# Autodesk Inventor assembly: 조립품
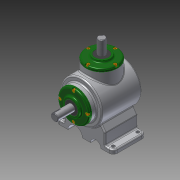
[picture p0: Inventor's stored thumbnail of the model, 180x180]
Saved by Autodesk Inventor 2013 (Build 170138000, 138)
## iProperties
Created: 2018-08
Part Number: 조립품
Document SubType Name: Assembly
Designer: Administrator
Author: Administrator
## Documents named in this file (14)
- C:\Users\Administrator\Desktop\480807V1016\조립품.iam
- C:\Users\Administrator\Desktop\480807V1016\본체.ipt
- C:\Users\Administrator\Desktop\480807V1016\메인 베벨기어.ipt
- C:\Users\Administrator\Desktop\480807V1016\메인 축.ipt
- 메인 축.ipt
- C:\Users\Administrator\Desktop\480807V1016\베어링 6203.ipt
- C:\Users\Administrator\Desktop\480807V1016\볼트 M4.ipt
- C:\Users\Administrator\Desktop\480807V1016\서브 베벨기어.ipt
- C:\Users\Administrator\Desktop\480807V1016\서브 축.ipt
- 서브 축.ipt
- C:\Users\Administrator\Desktop\480807V1016\오일실 17 32 8.ipt
- C:\Users\Administrator\Desktop\480807V1016\커버.ipt
- C:\Users\Administrator\Desktop\480807V1016\키 4x4.ipt
- C:\Users\Administrator\Desktop\480807V1016\키 5x5.ipt
